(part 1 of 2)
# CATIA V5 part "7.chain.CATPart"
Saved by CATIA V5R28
Part number: Chain
Bounding box of the stored display mesh (mm): x -3.5 to 3.5, y -378.076 to 79.358, z -79.308 to 79.467
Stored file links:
  D:\Catia Cycle design\7.chain.CATPart
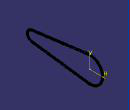
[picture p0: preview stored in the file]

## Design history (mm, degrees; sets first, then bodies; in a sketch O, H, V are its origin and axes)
Set1
  Sketch1 on yz-plane, origin (0, 0, 0), H (0, 1, 0), V (0, 0, 1)
    arc A1 centre (0, 0) radius 75 from (-9.8193, -74.3544) to (-9.8193, 74.3544) ccw
    arc A2 centre (-343.71, 0) radius 30 from (-347.6377, 29.7418) to (-347.6377, -29.7418) ccw
    point P1 (-343.71, 0)
    line L1 (-347.6377, -29.7418) -> (-9.8193, -74.3544)
    line L2 (-347.6377, 29.7418) -> (-9.8193, 74.3544)
    radius A1 = 75
    radius A2 = 30
    distance P1 O = 343.71
    coincidence: P1 H
    tangency: L1 A1, L1 A2, L2 A1, L2 A2
  Sketch2 on yz-plane, origin (0, 0, 0), H (0, 1, 0), V (0, 0, 1)
    circle A1 centre (-9.8193, 74.3544) radius 2.25
    point P1 (-9.8193, 74.3544)
    reference projected point E1 (-9.8193, 74.3544) from vertex [element of Sketch1 | element of Sketch1]
    point P2 (2.1649, 74.9687)
    reference projected arc E2 centre (0, 0) radius 75 from (-9.8193, -74.3544) to (-9.8193, 74.3544) ccw from Sketch1.A1
    circle A2 centre (2.1649, 74.9687) radius 2.25
    circle A3 centre (14.0938, 73.6639) radius 2.25
    circle A4 centre (25.6618, 70.4732) radius 2.25
    circle A5 centre (36.5729, 65.4784) radius 2.25
    circle A6 centre (46.5478, 58.8074) radius 2.25
    circle A7 centre (55.331, 50.6309) radius 2.25
    circle A8 centre (62.6977, 41.1582) radius 2.25
    circle A9 centre (68.4594, 30.6319) radius 2.25
    circle A10 centre (72.4685, 19.3214) radius 2.25
    circle A11 centre (74.6224, 7.5163) radius 2.25
    circle A12 centre (74.866, -4.4812) radius 2.25
    circle A13 centre (73.193, -16.364) radius 2.25
    circle A14 centre (69.6463, -27.8279) radius 2.25
    circle A15 centre (64.3166, -38.5794) radius 2.25
    circle A16 centre (57.3405, -48.3433) radius 2.25
    circle A17 centre (48.8964, -56.8695) radius 2.25
    circle A18 centre (39.2005, -63.94) radius 2.25
    circle A19 centre (28.5012, -69.3735) radius 2.25
    circle A20 centre (17.0722, -73.0311) radius 2.25
    circle A21 centre (5.2061, -74.8191) radius 2.25
    point P23 (-6.7932, -74.6917)
    circle A22 centre (-6.7932, -74.6917) radius 2.25
    point P24 (-18.6979, -73.1819)
    circle A23 centre (-18.6979, -73.1819) radius 2.25
    reference projected line E3 (-347.6377, -29.7418) -> (-9.8193, -74.3544) from Sketch1.L1
    point P25 (-30.5946, -71.6108)
    reference projected line E4 (-347.6377, -29.7418) -> (-9.8193, -74.3544) from Sketch1.L1
    circle A24 centre (-30.5946, -71.6108) radius 2.25
    circle A25 centre (-42.4913, -70.0397) radius 2.25
    circle A26 centre (-54.388, -68.4686) radius 2.25
    circle A27 centre (-66.2847, -66.8976) radius 2.25
    circle A28 centre (-78.1814, -65.3265) radius 2.25
    circle A29 centre (-90.0781, -63.7554) radius 2.25
    circle A30 centre (-101.9748, -62.1843) radius 2.25
    circle A31 centre (-113.8715, -60.6132) radius 2.25
    circle A32 centre (-125.7682, -59.0421) radius 2.25
    circle A33 centre (-137.6649, -57.471) radius 2.25
    circle A34 centre (-149.5616, -55.8999) radius 2.25
    circle A35 centre (-161.4584, -54.3288) radius 2.25
    circle A36 centre (-173.3551, -52.7577) radius 2.25
    circle A37 centre (-185.2518, -51.1866) radius 2.25
    circle A38 centre (-197.1485, -49.6155) radius 2.25
    circle A39 centre (-209.0452, -48.0444) radius 2.25
    circle A40 centre (-220.9419, -46.4734) radius 2.25
    circle A41 centre (-232.8386, -44.9023) radius 2.25
    circle A42 centre (-244.7353, -43.3312) radius 2.25
    circle A43 centre (-256.632, -41.7601) radius 2.25
    circle A44 centre (-268.5287, -40.189) radius 2.25
    circle A45 centre (-280.4254, -38.6179) radius 2.25
    circle A46 centre (-292.3221, -37.0468) radius 2.25
    circle A47 centre (-304.2189, -35.4757) radius 2.25
    circle A48 centre (-316.1156, -33.9046) radius 2.25
    circle A49 centre (-328.0123, -32.3335) radius 2.25
    point P52 (-339.909, -30.7624)
    circle A50 centre (-339.909, -30.7624) radius 2.25
    point P53 (-351.7634, -28.8988)
    circle A51 centre (-351.7634, -28.8988) radius 2.25
    construction circle A52 centre (-343.71, 0) radius 15.1604
    reference projected arc E5 centre (-343.71, 0) radius 30 from (-347.6377, 29.7418) to (-347.6377, -29.7418) ccw from Sketch1.A2
    reference projected arc E6 centre (-343.71, 0) radius 30 from (-347.6377, 29.7418) to (-347.6377, -29.7418) ccw from Sketch1.A2
    point P55 (-362.4451, -23.4307)
    reference projected arc E7 centre (-343.71, 0) radius 30 from (-347.6377, 29.7418) to (-347.6377, -29.7418) ccw from Sketch1.A2
    circle A53 centre (-362.4451, -23.4307) radius 2.25
    circle A54 centre (-370.1292, -14.2136) radius 2.25
    circle A55 centre (-373.5862, -2.7223) radius 2.25
    circle A56 centre (-372.2631, 9.2045) radius 2.25
    circle A57 centre (-366.3714, 19.6586) radius 2.25
    point P61 (-356.8539, 26.9673)
    circle A58 centre (-356.8539, 26.9673) radius 2.25
    point P62 (-345.2582, 30.056)
    circle A59 centre (-345.2582, 30.056) radius 2.25
    reference projected line E8 (-9.8193, 74.3544) -> (-347.6377, 29.7418) from Sketch1.L2
    point P63 (-333.3615, 31.6271)
    reference projected line E9 (-9.8193, 74.3544) -> (-347.6377, 29.7418) from Sketch1.L2
    circle A60 centre (-333.3615, 31.6271) radius 2.25
    circle A61 centre (-321.4648, 33.1982) radius 2.25
    circle A62 centre (-309.5681, 34.7693) radius 2.25
    circle A63 centre (-297.6714, 36.3404) radius 2.25
    circle A64 centre (-285.7747, 37.9115) radius 2.25
    circle A65 centre (-273.878, 39.4826) radius 2.25
    circle A66 centre (-261.9813, 41.0537) radius 2.25
    circle A67 centre (-250.0846, 42.6247) radius 2.25
    circle A68 centre (-238.1878, 44.1958) radius 2.25
    circle A69 centre (-226.2911, 45.7669) radius 2.25
    circle A70 centre (-214.3944, 47.338) radius 2.25
    circle A71 centre (-202.4977, 48.9091) radius 2.25
    circle A72 centre (-190.601, 50.4802) radius 2.25
    circle A73 centre (-178.7043, 52.0513) radius 2.25
    circle A74 centre (-166.8076, 53.6224) radius 2.25
    circle A75 centre (-154.9109, 55.1935) radius 2.25
    circle A76 centre (-143.0142, 56.7646) radius 2.25
    circle A77 centre (-131.1175, 58.3357) radius 2.25
    circle A78 centre (-119.2208, 59.9068) radius 2.25
    circle A79 centre (-107.3241, 61.4778) radius 2.25
    point P84 (-95.4273, 63.0489)
    circle A80 centre (-95.4273, 63.0489) radius 2.25
    point P85 (-81.1513, 64.9343)
    circle A81 centre (-81.1513, 64.9343) radius 2.25
    point P86 (-66.8752, 66.8196)
    reference projected line E10 (-9.8193, 74.3544) -> (-347.6377, 29.7418) from Sketch1.L2
    circle A82 centre (-66.8752, 66.8196) radius 2.25
    circle A83 centre (-52.5992, 68.7049) radius 2.25
    circle A84 centre (-38.3231, 70.5902) radius 2.25
    circle A85 centre (-24.0471, 72.4755) radius 2.25
    radius A1 = 2.25
    distance P1 P2 = 12
    distance P23 P24 = 12
    distance P24 P25 = 12
    distance P52 P53 = 12
    distance P53 P55 = 12
    distance P61 P62 = 12
    distance P62 P63 = 12
    distance P84 P85 = 14.4
    distance P85 P86 = 14.4
    coincidence: P1 E1, P2 E2, P24 E3, P25 E4, P53 E6, P55 E7, P62 E8, P63 E9, P86 E10
    fix: P1, P23, P52, P61, P62, P84
    concentricity: E5 A52
Body1 (main body)
  Pad1: profile Sketch2, direction (1, 0, 0), length 3.5, mirrored extent
  Sketch3 on end face of Pad1, origin (3.5, 0, 0), H (0, 1, 0), V (0, 0, 1)
    arc A1 centre (-9.8193, 74.3544) radius 4.5 from (-8.6557, 78.7014) to (-8.2173, 70.1492) ccw
    circle A2 centre (-9.8193, 74.3544) radius 2.25
    arc A3 centre (2.1649, 74.9687) radius 4.5 from (1.0013, 70.6218) to (0.5629, 79.1739) ccw
    circle A4 centre (2.1649, 74.9687) radius 2.25
    arc A5 centre (-4.777, 93.1912) radius 15 from (-8.6557, 78.7014) to (0.5629, 79.1739) ccw
    arc A6 centre (-2.8774, 56.1319) radius 15 from (-8.2173, 70.1492) to (1.0013, 70.6218) cw
    circle A7 centre (-333.3615, 31.6271) radius 2.25
    circle A8 centre (-321.4648, 33.1982) radius 2.25
    arc A9 centre (-321.4648, 33.1982) radius 4.5 from (-322.2769, 28.7721) to (-323.3981, 37.2617) ccw
    arc A10 centre (-329.8423, 50.8069) radius 15 from (-332.5494, 36.0532) to (-323.3981, 37.2617) ccw
    arc A11 centre (-333.3615, 31.6271) radius 4.5 from (-332.5494, 36.0532) to (-331.4282, 27.5636) ccw
    arc A12 centre (-324.984, 14.0184) radius 15 from (-331.4282, 27.5636) to (-322.2769, 28.7721) cw
    circle A13 centre (-95.4273, 63.0489) radius 2.25
    circle A14 centre (-81.1513, 64.9343) radius 2.25
    arc A15 centre (-81.1513, 64.9343) radius 4.5 from (-82.251, 60.5707) to (-83.3461, 68.8627) ccw
    arc A16 centre (-90.6619, 81.9577) radius 15 from (-94.3276, 67.4125) to (-83.3461, 68.8627) ccw
    arc A17 centre (-95.4273, 63.0489) radius 4.5 from (-94.3276, 67.4125) to (-93.2326, 59.1205) ccw
    arc A18 centre (-85.9167, 46.0255) radius 15 from (-93.2326, 59.1205) to (-82.251, 60.5707) cw
    circle A19 centre (-30.5946, -71.6108) radius 2.25
    circle A20 centre (-18.6979, -73.1819) radius 2.25
    arc A21 centre (-18.6979, -73.1819) radius 4.5 from (-20.6311, -77.2455) to (-19.51, -68.7558) ccw
    arc A22 centre (-22.217, -54.0021) radius 15 from (-28.6613, -67.5473) to (-19.51, -68.7558) ccw
    arc A23 centre (-30.5946, -71.6108) radius 4.5 from (-28.6613, -67.5473) to (-29.7824, -76.0369) ccw
    arc A24 centre (-27.0754, -90.7906) radius 15 from (-29.7824, -76.0369) to (-20.6311, -77.2455) cw
    reference projected point E1 (-9.8193, 74.3544) from vertex [element of Sketch1 | element of Sketch1]
    point P32 (2.1649, 74.9687)
    reference projected circle E2 centre (2.1649, 74.9687) radius 2.25 from edge [face of Pad1 from Sketch2.A2 | end face of Pad1]
    point P33 (14.0938, 73.6639)
    reference projected circle E3 centre (14.0938, 73.6639) radius 2.25 from edge [face of Pad1 from Sketch2.A3 | end face of Pad1]
    point P40 (25.6618, 70.4732)
    arc A25 centre (14.0938, 73.6639) radius 4.5 from (16.567, 77.4233) to (14.2901, 69.1682) ccw
    circle A26 centre (14.0938, 73.6639) radius 2.25
    arc A27 centre (25.6618, 70.4732) radius 4.5 from (23.1886, 66.7138) to (25.4655, 74.9689) ccw
    circle A28 centre (25.6618, 70.4732) radius 2.25
    arc A29 centre (24.8111, 89.9546) radius 15 from (16.567, 77.4233) to (25.4655, 74.9689) ccw
    arc A30 centre (14.9445, 54.1824) radius 15 from (14.2901, 69.1682) to (23.1886, 66.7138) cw
    point P49 (46.5478, 58.8074)
    arc A31 centre (36.5729, 65.4784) radius 4.5 from (40.1041, 68.2678) to (35.3436, 61.1496) ccw
    circle A32 centre (36.5729, 65.4784) radius 2.25
    arc A33 centre (46.5478, 58.8074) radius 4.5 from (43.0165, 56.018) to (47.7771, 63.1362) ccw
    circle A34 centre (46.5478, 58.8074) radius 2.25
    arc A35 centre (51.8749, 77.5656) radius 15 from (40.1041, 68.2678) to (47.7771, 63.1362) ccw
    arc A36 centre (31.2458, 46.7202) radius 15 from (35.3436, 61.1496) to (43.0165, 56.018) cw
    point P58 (62.6977, 41.1582)
    arc A37 centre (55.331, 50.6309) radius 4.5 from (59.5609, 52.1664) to (52.8011, 46.9094) ccw
    circle A38 centre (55.331, 50.6309) radius 2.25
    arc A39 centre (62.6977, 41.1582) radius 4.5 from (58.4678, 39.6227) to (65.2276, 44.8797) ccw
    circle A40 centre (62.6977, 41.1582) radius 2.25
    arc A41 centre (73.6606, 57.2847) radius 15 from (59.5609, 52.1664) to (65.2276, 44.8797) ccw
    arc A42 centre (44.3681, 34.5043) radius 15 from (52.8011, 46.9094) to (58.4678, 39.6227) cw
    point P67 (72.4685, 19.3214)
    arc A43 centre (68.4594, 30.6319) radius 4.5 from (72.9576, 30.7573) to (64.8863, 27.8964) ccw
    circle A44 centre (68.4594, 30.6319) radius 2.25
    arc A45 centre (72.4685, 19.3214) radius 4.5 from (67.9702, 19.196) to (76.0416, 22.057) ccw
    circle A46 centre (72.4685, 19.3214) radius 2.25
    arc A47 centre (87.9518, 31.1754) radius 15 from (72.9576, 30.7573) to (76.0416, 22.057) ccw
    arc A48 centre (52.9761, 18.7779) radius 15 from (64.8863, 27.8964) to (67.9702, 19.196) cw
    point P76 (74.866, -4.4812)
    arc A49 centre (74.6224, 7.5163) radius 4.5 from (78.9313, 6.2189) to (70.3697, 6.0451) ccw
    circle A50 centre (74.6224, 7.5163) radius 2.25
    arc A51 centre (74.866, -4.4812) radius 4.5 from (70.5571, -3.1838) to (79.1187, -3.01) ccw
    circle A52 centre (74.866, -4.4812) radius 2.25
    arc A53 centre (93.2944, 1.8942) radius 15 from (78.9313, 6.2189) to (79.1187, -3.01) ccw
    arc A54 centre (56.1941, 1.1409) radius 15 from (70.3697, 6.0451) to (70.5571, -3.1838) cw
    point P85 (69.6463, -27.8279)
    arc A55 centre (73.193, -16.364) radius 4.5 from (76.8742, -18.9523) to (68.6934, -16.4213) ccw
    circle A56 centre (73.193, -16.364) radius 2.25
    arc A57 centre (69.6463, -27.8279) radius 4.5 from (65.9651, -25.2397) to (74.1459, -27.7707) ccw
    circle A58 centre (69.6463, -27.8279) radius 2.25
    arc A59 centre (89.1447, -27.5798) radius 15 from (76.8742, -18.9523) to (74.1459, -27.7707) ccw
    arc A60 centre (53.6946, -16.6122) radius 15 from (68.6934, -16.4213) to (65.9651, -25.2397) cw
    point P94 (57.3405, -48.3433)
    arc A61 centre (64.3166, -38.5794) radius 4.5 from (66.9955, -42.1952) to (60.0279, -37.2169) ccw
    circle A62 centre (64.3166, -38.5794) radius 2.25
    arc A63 centre (57.3405, -48.3433) radius 4.5 from (54.6616, -44.7275) to (61.6292, -49.7058) ccw
    circle A64 centre (57.3405, -48.3433) radius 2.25
    arc A65 centre (75.9251, -54.2477) radius 15 from (66.9955, -42.1952) to (61.6292, -49.7058) ccw
    arc A66 centre (45.732, -32.675) radius 15 from (60.0279, -37.2169) to (54.6616, -44.7275) cw
    point P103 (39.2005, -63.94)
    arc A67 centre (48.8964, -56.8695) radius 4.5 from (50.3004, -61.1449) to (45.2548, -54.2258) ccw
    circle A68 centre (48.8964, -56.8695) radius 2.25
    arc A69 centre (39.2005, -63.94) radius 4.5 from (37.7965, -59.6646) to (42.8421, -66.5837) ccw
    circle A70 centre (39.2005, -63.94) radius 2.25
    arc A71 centre (54.9805, -75.3961) radius 15 from (50.3004, -61.1449) to (42.8421, -66.5837) ccw
    arc A72 centre (33.1164, -45.4134) radius 15 from (45.2548, -54.2258) to (37.7965, -59.6646) cw
    point P112 (17.0722, -73.0311)
    arc A73 centre (28.5012, -69.3735) radius 4.5 from (28.4875, -73.8735) to (25.8774, -65.7176) ccw
    circle A74 centre (28.5012, -69.3735) radius 2.25
    arc A75 centre (17.0722, -73.0311) radius 4.5 from (17.0858, -68.5311) to (19.6959, -76.687) ccw
    circle A76 centre (17.0722, -73.0311) radius 2.25
    arc A77 centre (28.4419, -88.8734) radius 15 from (28.4875, -73.8735) to (19.6959, -76.687) ccw
    arc A78 centre (17.1314, -53.5312) radius 15 from (25.8774, -65.7176) to (17.0858, -68.5311) cw
    point P121 (-6.7932, -74.6917)
    arc A79 centre (5.2061, -74.8191) radius 4.5 from (3.7761, -79.0858) to (3.867, -70.5229) ccw
    circle A80 centre (5.2061, -74.8191) radius 2.25
    arc A81 centre (-6.7932, -74.6917) radius 4.5 from (-5.3632, -70.425) to (-5.4541, -78.9879) ccw
    circle A82 centre (-6.7932, -74.6917) radius 2.25
    arc A83 centre (-0.9905, -93.3083) radius 15 from (3.7761, -79.0858) to (-5.4541, -78.9879) ccw
    arc A84 centre (-0.5966, -56.2025) radius 15 from (3.867, -70.5229) to (-5.3632, -70.425) cw
    point P124 (-30.5946, -71.6108)
    point P125 (-18.6979, -73.1819)
    reference projected circle E4 centre (-18.6979, -73.1819) radius 2.25 from edge [face of Pad1 from Sketch2.A23 | end face of Pad1]
    reference projected circle E5 centre (-30.5946, -71.6108) radius 2.25 from edge [face of Pad1 from Sketch2.A24 | end face of Pad1]
    reference projected circle E6 centre (-18.6979, -73.1819) radius 2.25 from edge [face of Pad1 from Sketch2.A23 | end face of Pad1]
    point P126 (-42.4913, -70.0397)
    reference projected circle E7 centre (-42.4913, -70.0397) radius 2.25 from edge [face of Pad1 from Sketch2.A25 | end face of Pad1]
    point P133 (-54.388, -68.4686)
    point P134 (-42.4913, -70.0397)
    circle A85 centre (-54.388, -68.4686) radius 2.25
    circle A86 centre (-42.4913, -70.0397) radius 2.25
    arc A87 centre (-42.4913, -70.0397) radius 4.5 from (-44.4245, -74.1033) to (-43.3034, -65.6136) ccw
    arc A88 centre (-46.0105, -50.8599) radius 15 from (-52.4547, -64.4051) to (-43.3034, -65.6136) ccw
    arc A89 centre (-54.388, -68.4686) radius 4.5 from (-52.4547, -64.4051) to (-53.5759, -72.8948) ccw
    arc A90 centre (-50.8688, -87.6485) radius 15 from (-53.5759, -72.8948) to (-44.4245, -74.1033) cw
    point P142 (-78.1814, -65.3265)
    point P143 (-66.2847, -66.8976)
    circle A91 centre (-78.1814, -65.3265) radius 2.25
    circle A92 centre (-66.2847, -66.8976) radius 2.25
    arc A93 centre (-66.2847, -66.8976) radius 4.5 from (-68.218, -70.9611) to (-67.0968, -62.4714) ccw
    arc A94 centre (-69.8039, -47.7177) radius 15 from (-76.2481, -61.2629) to (-67.0968, -62.4714) ccw
    arc A95 centre (-78.1814, -65.3265) radius 4.5 from (-76.2481, -61.2629) to (-77.3693, -69.7526) ccw
    arc A96 centre (-74.6622, -84.5063) radius 15 from (-77.3693, -69.7526) to (-68.218, -70.9611) cw
    point P151 (-101.9748, -62.1843)
    point P152 (-90.0781, -63.7554)
    circle A97 centre (-101.9748, -62.1843) radius 2.25
    circle A98 centre (-90.0781, -63.7554) radius 2.25
    arc A99 centre (-90.0781, -63.7554) radius 4.5 from (-92.0114, -67.8189) to (-90.8902, -59.3293) ccw
    arc A100 centre (-93.5973, -44.5756) radius 15 from (-100.0415, -58.1207) to (-90.8902, -59.3293) ccw
    arc A101 centre (-101.9748, -62.1843) radius 4.5 from (-100.0415, -58.1207) to (-101.1627, -66.6104) ccw
    arc A102 centre (-98.4556, -81.3641) radius 15 from (-101.1627, -66.6104) to (-92.0114, -67.8189) cw
    point P160 (-125.7682, -59.0421)
    point P161 (-113.8715, -60.6132)
    circle A103 centre (-125.7682, -59.0421) radius 2.25
    circle A104 centre (-113.8715, -60.6132) radius 2.25
    arc A105 centre (-113.8715, -60.6132) radius 4.5 from (-115.8048, -64.6767) to (-114.6836, -56.1871) ccw
    arc A106 centre (-117.3907, -41.4334) radius 15 from (-123.835, -54.9785) to (-114.6836, -56.1871) ccw
    arc A107 centre (-125.7682, -59.0421) radius 4.5 from (-123.835, -54.9785) to (-124.9561, -63.4682) ccw
    arc A108 centre (-122.249, -78.2219) radius 15 from (-124.9561, -63.4682) to (-115.8048, -64.6767) cw
    point P169 (-149.5616, -55.8999)
    point P170 (-137.6649, -57.471)
    circle A109 centre (-149.5616, -55.8999) radius 2.25
    circle A110 centre (-137.6649, -57.471) radius 2.25
    arc A111 centre (-137.6649, -57.471) radius 4.5 from (-139.5982, -61.5346) to (-138.4771, -53.0449) ccw
    arc A112 centre (-141.1841, -38.2912) radius 15 from (-147.6284, -51.8364) to (-138.4771, -53.0449) ccw
    arc A113 centre (-149.5616, -55.8999) radius 4.5 from (-147.6284, -51.8364) to (-148.7495, -60.326) ccw
    arc A114 centre (-146.0425, -75.0797) radius 15 from (-148.7495, -60.326) to (-139.5982, -61.5346) cw
    point P178 (-173.3551, -52.7577)
    point P179 (-161.4584, -54.3288)
    circle A115 centre (-173.3551, -52.7577) radius 2.25
    circle A116 centre (-161.4584, -54.3288) radius 2.25
    arc A117 centre (-161.4584, -54.3288) radius 4.5 from (-163.3916, -58.3924) to (-162.2705, -49.9027) ccw
    arc A118 centre (-164.9775, -35.149) radius 15 from (-171.4218, -48.6942) to (-162.2705, -49.9027) ccw
    arc A119 centre (-173.3551, -52.7577) radius 4.5 from (-171.4218, -48.6942) to (-172.5429, -57.1838) ccw
    arc A120 centre (-169.8359, -71.9375) radius 15 from (-172.5429, -57.1838) to (-163.3916, -58.3924) cw
    point P187 (-197.1485, -49.6155)
    point P188 (-185.2518, -51.1866)
    circle A121 centre (-197.1485, -49.6155) radius 2.25
    circle A122 centre (-185.2518, -51.1866) radius 2.25
    arc A123 centre (-185.2518, -51.1866) radius 4.5 from (-187.185, -55.2502) to (-186.0639, -46.7605) ccw
    arc A124 centre (-188.771, -32.0068) radius 15 from (-195.2152, -45.552) to (-186.0639, -46.7605) ccw
    arc A125 centre (-197.1485, -49.6155) radius 4.5 from (-195.2152, -45.552) to (-196.3364, -54.0417) ccw
    arc A126 centre (-193.6293, -68.7954) radius 15 from (-196.3364, -54.0417) to (-187.185, -55.2502) cw
    point P196 (-220.9419, -46.4734)
    point P197 (-209.0452, -48.0444)
    circle A127 centre (-220.9419, -46.4734) radius 2.25
    circle A128 centre (-209.0452, -48.0444) radius 2.25
    arc A129 centre (-209.0452, -48.0444) radius 4.5 from (-210.9785, -52.108) to (-209.8573, -43.6183) ccw
    arc A130 centre (-212.5644, -28.8646) radius 15 from (-219.0086, -42.4098) to (-209.8573, -43.6183) ccw
    arc A131 centre (-220.9419, -46.4734) radius 4.5 from (-219.0086, -42.4098) to (-220.1298, -50.8995) ccw
    arc A132 centre (-217.4227, -65.6532) radius 15 from (-220.1298, -50.8995) to (-210.9785, -52.108) cw
    point P205 (-244.7353, -43.3312)
    point P206 (-232.8386, -44.9023)
    circle A133 centre (-244.7353, -43.3312) radius 2.25
    circle A134 centre (-232.8386, -44.9023) radius 2.25
    arc A135 centre (-232.8386, -44.9023) radius 4.5 from (-234.7719, -48.9658) to (-233.6507, -40.4762) ccw
    arc A136 centre (-236.3578, -25.7224) radius 15 from (-242.802, -39.2676) to (-233.6507, -40.4762) ccw
    arc A137 centre (-244.7353, -43.3312) radius 4.5 from (-242.802, -39.2676) to (-243.9232, -47.7573) ccw
    arc A138 centre (-241.2161, -62.511) radius 15 from (-243.9232, -47.7573) to (-234.7719, -48.9658) cw
    point P214 (-268.5287, -40.189)
    point P215 (-256.632, -41.7601)
    circle A139 centre (-268.5287, -40.189) radius 2.25
    circle A140 centre (-256.632, -41.7601) radius 2.25
    arc A141 centre (-256.632, -41.7601) radius 4.5 from (-258.5653, -45.8236) to (-257.4441, -37.334) ccw
    arc A142 centre (-260.1512, -22.5803) radius 15 from (-266.5955, -36.1254) to (-257.4441, -37.334) ccw
    arc A143 centre (-268.5287, -40.189) radius 4.5 from (-266.5955, -36.1254) to (-267.7166, -44.6151) ccw
    arc A144 centre (-265.0095, -59.3688) radius 15 from (-267.7166, -44.6151) to (-258.5653, -45.8236) cw
    point P223 (-292.3221, -37.0468)
    point P224 (-280.4254, -38.6179)
    circle A145 centre (-292.3221, -37.0468) radius 2.25
    circle A146 centre (-280.4254, -38.6179) radius 2.25
    arc A147 centre (-280.4254, -38.6179) radius 4.5 from (-282.3587, -42.6814) to (-281.2376, -34.1918) ccw
    arc A148 centre (-283.9446, -19.4381) radius 15 from (-290.3889, -32.9833) to (-281.2376, -34.1918) ccw
    arc A149 centre (-292.3221, -37.0468) radius 4.5 from (-290.3889, -32.9833) to (-291.51, -41.4729) ccw
    arc A150 centre (-288.803, -56.2266) radius 15 from (-291.51, -41.4729) to (-282.3587, -42.6814) cw
    point P232 (-316.1156, -33.9046)
    point P233 (-304.2189, -35.4757)
    circle A151 centre (-316.1156, -33.9046) radius 2.25
    circle A152 centre (-304.2189, -35.4757) radius 2.25
    arc A153 centre (-304.2189, -35.4757) radius 4.5 from (-306.1521, -39.5393) to (-305.031, -31.0496) ccw
    arc A154 centre (-307.738, -16.2959) radius 15 from (-314.1823, -29.8411) to (-305.031, -31.0496) ccw
    arc A155 centre (-316.1156, -33.9046) radius 4.5 from (-314.1823, -29.8411) to (-315.3034, -38.3307) ccw
    arc A156 centre (-312.5964, -53.0844) radius 15 from (-315.3034, -38.3307) to (-306.1521, -39.5393) cw
    point P241 (-339.909, -30.7624)
    point P242 (-328.0123, -32.3335)
    circle A157 centre (-339.909, -30.7624) radius 2.25
    circle A158 centre (-328.0123, -32.3335) radius 2.25
    arc A159 centre (-328.0123, -32.3335) radius 4.5 from (-329.9455, -36.3971) to (-328.8244, -27.9074) ccw
    arc A160 centre (-331.5315, -13.1537) radius 15 from (-337.9757, -26.6989) to (-328.8244, -27.9074) ccw
    arc A161 centre (-339.909, -30.7624) radius 4.5 from (-337.9757, -26.6989) to (-339.0969, -35.1885) ccw
    arc A162 centre (-336.3898, -49.9423) radius 15 from (-339.0969, -35.1885) to (-329.9455, -36.3971) cw
    circle A163 centre (-362.4451, -23.4307) radius 2.25
    circle A164 centre (-351.7634, -28.8988) radius 2.25
    arc A165 centre (-351.7634, -28.8988) radius 4.5 from (-354.947, -32.0792) to (-351.0448, -24.4566) ccw
    arc A166 centre (-348.6495, -9.6491) radius 15 from (-359.2615, -20.2503) to (-351.0448, -24.4566) ccw
    arc A167 centre (-362.4451, -23.4307) radius 4.5 from (-359.2615, -20.2503) to (-363.1637, -27.8729) ccw
    arc A168 centre (-365.5589, -42.6804) radius 15 from (-363.1637, -27.8729) to (-354.947, -32.0792) cw
    point P252 (-351.7634, -28.8988)
    point P253 (-362.4451, -23.4307)
    point P254 (-370.1292, -14.2136)
    reference projected circle E8 centre (-351.7634, -28.8988) radius 2.25 from edge [face of Pad1 from Sketch2.A51 | end face of Pad1]
    reference projected circle E9 centre (-362.4451, -23.4307) radius 2.25 from edge [face of Pad1 from Sketch2.A53 | end face of Pad1]
    reference projected circle E10 centre (-370.1292, -14.2136) radius 2.25 from edge [face of Pad1 from Sketch2.A54 | end face of Pad1]
    construction circle A169 centre (-343.71, 0) radius 8.6889
    reference projected arc E11 centre (-343.71, 0) radius 30 from (-347.6377, 29.7418) to (-347.6377, -29.7418) ccw from Sketch1.A2
    point P262 (-370.1292, -14.2136)
    point P263 (-373.5862, -2.7223)
    circle A170 centre (-373.5862, -2.7223) radius 2.25
    circle A171 centre (-370.1292, -14.2136) radius 2.25
    arc A172 centre (-370.1292, -14.2136) radius 4.5 from (-374.6283, -14.1212) to (-366.4279, -11.6542) ccw
    arc A173 centre (-354.0903, -3.1228) radius 15 from (-369.0872, -2.8147) to (-366.4279, -11.6542) ccw
    arc A174 centre (-373.5862, -2.7223) radius 4.5 from (-369.0872, -2.8147) to (-377.2875, -5.2817) ccw
    arc A175 centre (-389.6251, -13.8131) radius 15 from (-377.2875, -5.2817) to (-374.6283, -14.1212) cw
    point P272 (-372.2631, 9.2045)
    point P273 (-366.3714, 19.6586)
    circle A176 centre (-366.3714, 19.6586) radius 2.25
    circle A177 centre (-372.2631, 9.2045) radius 2.25
    arc A178 centre (-372.2631, 9.2045) radius 4.5 from (-375.3134, 12.5129) to (-367.8531, 8.3086) ccw
    arc A179 centre (-353.1535, 5.3221) radius 15 from (-363.3211, 16.3502) to (-367.8531, 8.3086) ccw
    arc A180 centre (-366.3714, 19.6586) radius 4.5 from (-363.3211, 16.3502) to (-370.7813, 20.5546) ccw
    arc A181 centre (-385.481, 23.541) radius 15 from (-370.7813, 20.5546) to (-375.3134, 12.5129) cw
    point P282 (-356.8539, 26.9673)
    point P283 (-345.2334, 29.9613)
    circle A182 centre (-345.2334, 29.9613) radius 2.25
    circle A183 centre (-356.8539, 26.9673) radius 2.25
    arc A184 centre (-356.8539, 26.9673) radius 4.5 from (-356.5814, 31.4591) to (-354.4448, 23.1665) ccw
    arc A185 centre (-346.4145, 10.4971) radius 15 from (-345.506, 25.4696) to (-354.4448, 23.1665) ccw
    arc A186 centre (-345.2334, 29.9613) radius 4.5 from (-345.506, 25.4696) to (-347.6425, 33.7621) ccw
    arc A187 centre (-355.6728, 46.4315) radius 15 from (-347.6425, 33.7621) to (-356.5814, 31.4591) cw
    point P286 (-333.3615, 31.6271)
    point P287 (-321.4648, 33.1982)
    point P288 (-309.5681, 34.7693)
    reference projected circle E12 centre (-333.3615, 31.6271) radius 2.25 from edge [face of Pad1 from Sketch2.A60 | end face of Pad1]
    reference projected circle E13 centre (-321.4648, 33.1982) radius 2.25 from edge [face of Pad1 from Sketch2.A61 | end face of Pad1]
    reference projected circle E14 centre (-309.5681, 34.7693) radius 2.25 from edge [face of Pad1 from Sketch2.A62 | end face of Pad1]
    point P295 (-309.5681, 34.7693)
    point P296 (-297.6714, 36.3404)
    point P297 (-285.7747, 37.9115)
    circle A188 centre (-309.5681, 34.7693) radius 2.25
    circle A189 centre (-297.6714, 36.3404) radius 2.25
    arc A190 centre (-297.6714, 36.3404) radius 4.5 from (-298.4835, 31.9143) to (-299.6047, 40.4039) ccw
    arc A191 centre (-306.0489, 53.9491) radius 15 from (-308.756, 39.1954) to (-299.6047, 40.4039) ccw
    arc A192 centre (-309.5681, 34.7693) radius 4.5 from (-308.756, 39.1954) to (-307.6348, 30.7057) ccw
    arc A193 centre (-301.1906, 17.1606) radius 15 from (-307.6348, 30.7057) to (-298.4835, 31.9143) cw
    point P306 (-285.7747, 37.9115)
    point P307 (-273.878, 39.4826)
    point P308 (-261.9813, 41.0537)
    circle A194 centre (-285.7747, 37.9115) radius 2.25
    circle A195 centre (-273.878, 39.4826) radius 2.25
    arc A196 centre (-273.878, 39.4826) radius 4.5 from (-274.6901, 35.0565) to (-275.8112, 43.5461) ccw
    arc A197 centre (-282.2555, 57.0913) radius 15 from (-284.9626, 42.3376) to (-275.8112, 43.5461) ccw
    arc A198 centre (-285.7747, 37.9115) radius 4.5 from (-284.9626, 42.3376) to (-283.8414, 33.8479) ccw
    arc A199 centre (-277.3972, 20.3027) radius 15 from (-283.8414, 33.8479) to (-274.6901, 35.0565) cw
    point P317 (-261.9813, 41.0537)
    point P318 (-250.0846, 42.6247)
    point P319 (-238.1878, 44.1958)
    circle A200 centre (-261.9813, 41.0537) radius 2.25
    circle A201 centre (-250.0846, 42.6247) radius 2.25
    arc A202 centre (-250.0846, 42.6247) radius 4.5 from (-250.8967, 38.1986) to (-252.0178, 46.6883) ccw
    arc A203 centre (-258.4621, 60.2335) radius 15 from (-261.1691, 45.4798) to (-252.0178, 46.6883) ccw
    arc A204 centre (-261.9813, 41.0537) radius 4.5 from (-261.1691, 45.4798) to (-260.048, 36.9901) ccw
    arc A205 centre (-253.6037, 23.4449) radius 15 from (-260.048, 36.9901) to (-250.8967, 38.1986) cw
    point P328 (-238.1878, 44.1958)
    point P329 (-226.2911, 45.7669)
    point P330 (-214.3944, 47.338)
    circle A206 centre (-238.1878, 44.1958) radius 2.25
    circle A207 centre (-226.2911, 45.7669) radius 2.25
    arc A208 centre (-226.2911, 45.7669) radius 4.5 from (-227.1033, 41.3408) to (-228.2244, 49.8305) ccw
    arc A209 centre (-234.6687, 63.3757) radius 15 from (-237.3757, 48.6219) to (-228.2244, 49.8305) ccw
    arc A210 centre (-238.1878, 44.1958) radius 4.5 from (-237.3757, 48.6219) to (-236.2546, 40.1323) ccw
    arc A211 centre (-229.8103, 26.5871) radius 15 from (-236.2546, 40.1323) to (-227.1033, 41.3408) cw
    point P339 (-214.3944, 47.338)
    point P340 (-202.4977, 48.9091)
    point P341 (-190.601, 50.4802)
    circle A212 centre (-214.3944, 47.338) radius 2.25
    circle A213 centre (-202.4977, 48.9091) radius 2.25
    arc A214 centre (-202.4977, 48.9091) radius 4.5 from (-203.3098, 44.483) to (-204.431, 52.9727) ccw
    arc A215 centre (-210.8752, 66.5178) radius 15 from (-213.5823, 51.7641) to (-204.431, 52.9727) ccw
    arc A216 centre (-214.3944, 47.338) radius 4.5 from (-213.5823, 51.7641) to (-212.4612, 43.2745) ccw
    arc A217 centre (-206.0169, 29.7293) radius 15 from (-212.4612, 43.2745) to (-203.3098, 44.483) cw
    point P350 (-190.601, 50.4802)
    point P351 (-178.7043, 52.0513)
    point P352 (-166.8076, 53.6224)
    circle A218 centre (-190.601, 50.4802) radius 2.25
    circle A219 centre (-178.7043, 52.0513) radius 2.25
    arc A220 centre (-178.7043, 52.0513) radius 4.5 from (-179.5164, 47.6252) to (-180.6376, 56.1148) ccw
    arc A221 centre (-187.0818, 69.66) radius 15 from (-189.7889, 54.9063) to (-180.6376, 56.1148) ccw
    arc A222 centre (-190.601, 50.4802) radius 4.5 from (-189.7889, 54.9063) to (-188.6677, 46.4167) ccw
    arc A223 centre (-182.2235, 32.8715) radius 15 from (-188.6677, 46.4167) to (-179.5164, 47.6252) cw
    point P361 (-166.8076, 53.6224)
    point P362 (-154.9109, 55.1935)
    point P363 (-143.0142, 56.7646)
    circle A224 centre (-166.8076, 53.6224) radius 2.25
    circle A225 centre (-154.9109, 55.1935) radius 2.25
    arc A226 centre (-154.9109, 55.1935) radius 4.5 from (-155.723, 50.7674) to (-156.8442, 59.257) ccw
    arc A227 centre (-163.2884, 72.8022) radius 15 from (-165.9955, 58.0485) to (-156.8442, 59.257) ccw
    arc A228 centre (-166.8076, 53.6224) radius 4.5 from (-165.9955, 58.0485) to (-164.8743, 49.5588) ccw
    arc A229 centre (-158.4301, 36.0137) radius 15 from (-164.8743, 49.5588) to (-155.723, 50.7674) cw
    point P372 (-143.0142, 56.7646)
    point P373 (-131.1175, 58.3357)
    point P374 (-119.2208, 59.9068)
    circle A230 centre (-143.0142, 56.7646) radius 2.25
    circle A231 centre (-131.1175, 58.3357) radius 2.25
    arc A232 centre (-131.1175, 58.3357) radius 4.5 from (-131.9296, 53.9096) to (-133.0507, 62.3992) ccw
    arc A233 centre (-139.495, 75.9444) radius 15 from (-142.2021, 61.1907) to (-133.0507, 62.3992) ccw
    arc A234 centre (-143.0142, 56.7646) radius 4.5 from (-142.2021, 61.1907) to (-141.0809, 52.701) ccw
    arc A235 centre (-134.6367, 39.1559) radius 15 from (-141.0809, 52.701) to (-131.9296, 53.9096) cw
    point P383 (-119.2208, 59.9068)
    point P384 (-107.3241, 61.4778)
    point P385 (-95.4273, 63.0489)
    circle A236 centre (-119.2208, 59.9068) radius 2.25
    circle A237 centre (-107.3241, 61.4778) radius 2.25
    arc A238 centre (-107.3241, 61.4778) radius 4.5 from (-108.1362, 57.0517) to (-109.2573, 65.5414) ccw
    arc A239 centre (-115.7016, 79.0866) radius 15 from (-118.4086, 64.3329) to (-109.2573, 65.5414) ccw
    arc A240 centre (-119.2208, 59.9068) radius 4.5 from (-118.4086, 64.3329) to (-117.2875, 55.8432) ccw
    arc A241 centre (-110.8432, 42.298) radius 15 from (-117.2875, 55.8432) to (-108.1362, 57.0517) cw
    point P388 (-95.4273, 63.0489)
    point P389 (-81.1513, 64.9343)
    point P390 (-66.8752, 66.8196)
    reference projected circle E15 centre (-95.4273, 63.0489) radius 2.25 from edge [face of Pad1 from Sketch2.A80 | end face of Pad1]
    reference projected circle E16 centre (-81.1513, 64.9343) radius 2.25 from edge [face of Pad1 from Sketch2.A81 | end face of Pad1]
    reference projected circle E17 centre (-66.8752, 66.8196) radius 2.25 from edge [face of Pad1 from Sketch2.A82 | end face of Pad1]
    reference projected circle E18 centre (-81.1513, 64.9343) radius 2.25 from edge [face of Pad1 from Sketch2.A81 | end face of Pad1]
    point P397 (-66.8752, 66.8196)
    point P398 (-66.8752, 66.8196)
    point P399 (-52.5992, 68.7049)
    circle A242 centre (-66.8752, 66.8196) radius 2.25
    circle A243 centre (-52.5992, 68.7049) radius 2.25
    arc A244 centre (-52.5992, 68.7049) radius 4.5 from (-53.6989, 64.3413) to (-54.794, 72.6334) ccw
    arc A245 centre (-62.1098, 85.7283) radius 15 from (-65.7755, 71.1831) to (-54.794, 72.6334) ccw
    arc A246 centre (-66.8752, 66.8196) radius 4.5 from (-65.7755, 71.1831) to (-64.6805, 62.8911) ccw
    arc A247 centre (-57.3646, 49.7961) radius 15 from (-64.6805, 62.8911) to (-53.6989, 64.3413) cw
    point P408 (-38.3231, 70.5902)
    point P409 (-38.3231, 70.5902)
    point P410 (-24.0471, 72.4755)
    circle A248 centre (-38.3231, 70.5902) radius 2.25
    circle A249 centre (-24.0471, 72.4755) radius 2.25
    arc A250 centre (-24.0471, 72.4755) radius 4.5 from (-25.1468, 68.1119) to (-26.2419, 76.404) ccw
    arc A251 centre (-33.5577, 89.4989) radius 15 from (-37.2234, 74.9537) to (-26.2419, 76.404) ccw
    arc A252 centre (-38.3231, 70.5902) radius 4.5 from (-37.2234, 74.9537) to (-36.1284, 66.6617) ccw
    arc A253 centre (-28.8125, 53.5667) radius 15 from (-36.1284, 66.6617) to (-25.1468, 68.1119) cw
    radius A2 = 2.25
    radius A1 = 4.5
    radius A4 = 2.25
    radius A3 = 4.5
    radius A5 = 15
    radius A6 = 15
    radius A7 = 2.25
    radius A8 = 2.25
    radius A9 = 4.5
    radius A12 = 15
    radius A13 = 2.25
    radius A14 = 2.25
    radius A15 = 4.5
    radius A18 = 15
    radius A19 = 2.25
    radius A20 = 2.25
    radius A21 = 4.5
    radius A24 = 15
    radius A23 = 4.5
    radius A22 = 15
    radius A163 = 2.25
    radius A164 = 2.25
    radius A165 = 4.5
    radius A168 = 15
    radius A167 = 4.5
    radius A163 = 2.25 (reference)
    radius A166 = 15
    radius A11 = 4.5
    radius A7 = 2.25 (reference)
    radius A10 = 15
    radius A17 = 4.5
    radius A13 = 2.25 (reference)
    radius A16 = 15
    tangency: A5 A3, A5 A1, A6 A1, A3 A6, A10 A9, A10 A11, A12 A11, A9 A12, A16 A15, A16 A17, A18 A17, A15 A18, A22 A21, A22 A23, A24 A23, A21 A24, A166 A165, A166 A167, A168 A167, A165 A168
    concentricity: E1 A2, P32 E2, A4 P32, E3 P33, P125 E4, P124 E5, A19 P124, A20 E6, P126 E7, P252 E8, P253 E9, P254 E10, A164 P252, A163 P253, E11 A169, P286 E12, P287 E13, P288 E14, A7 P286, A8 P287, P388 E15, P389 E16, P390 E17, A13 P388, A14 E18
  Pad2: profile Sketch3, direction (-1, 0, 0), length 1.5, opposite side length -0.5
  Mirror1: of Pad2, about yz-plane
  Sketch4 on yz-plane, origin (0, 0, 0), H (0, 1, 0), V (0, 0, 1)
    point P1 (13.183, 78.0707)
    point P2 (25.6618, 70.4732)
    reference projected circle E1 centre (25.6618, 70.4732) radius 2.25 from edge [face of Pad1 from Sketch2.A4 | end face of Pad1]
    point P7 (37.0961, 69.9479)
    arc A1 centre (25.6618, 70.4732) radius 4.5 from (28.703, 73.79) to (25.1386, 66.0037) ccw
    circle A2 centre (25.6618, 70.4732) radius 2.25
    circle A3 centre (36.5729, 65.4784) radius 2.25
    arc A4 centre (36.5729, 65.4784) radius 4.5 from (33.5318, 62.1616) to (37.0961, 69.9479) ccw
    arc A5 centre (38.8401, 84.8462) radius 15 from (28.703, 73.79) to (37.0961, 69.9479) ccw
    arc A6 centre (23.3946, 51.1054) radius 15 from (25.1386, 66.0037) to (33.5318, 62.1616) cw
    point P16 (57.235, 54.7082)
    arc A7 centre (46.5478, 58.8074) radius 4.5 from (50.4786, 60.9978) to (44.6438, 54.73) ccw
    circle A8 centre (46.5478, 58.8074) radius 2.25
    circle A9 centre (55.331, 50.6309) radius 2.25
    arc A10 centre (55.331, 50.6309) radius 4.5 from (51.4001, 48.4404) to (57.235, 54.7082) ccw
    arc A11 centre (63.5816, 68.2994) radius 15 from (50.4786, 60.9978) to (57.235, 54.7082) ccw
    arc A12 centre (38.2971, 41.1388) radius 15 from (44.6438, 54.73) to (51.4001, 48.4404) cw
    point P24 (71.5504, 33.9023)
    arc A13 centre (62.6977, 41.1582) radius 4.5 from (67.1184, 41.9994) to (59.6067, 37.8878) ccw
    circle A14 centre (62.6977, 41.1582) radius 2.25
    circle A15 centre (68.4594, 30.6319) radius 2.25
    arc A16 centre (68.4594, 30.6319) radius 4.5 from (64.0387, 29.7907) to (71.5504, 33.9023) ccw
    arc A17 centre (81.8539, 44.8036) radius 15 from (67.1184, 41.9994) to (71.5504, 33.9023) ccw
    arc A18 centre (49.3031, 26.9866) radius 15 from (59.6067, 37.8878) to (64.0387, 29.7907) cw
    point P33 (78.586, 9.647)
    arc A19 centre (72.4685, 19.3214) radius 4.5 from (76.9292, 18.7278) to (68.5049, 17.1908) ccw
    circle A20 centre (72.4685, 19.3214) radius 2.25
    circle A21 centre (74.6224, 7.5163) radius 2.25
    arc A22 centre (74.6224, 7.5163) radius 4.5 from (70.1617, 8.1099) to (78.586, 9.647) ccw
    arc A23 centre (91.7981, 16.7492) radius 15 from (76.9292, 18.7278) to (78.586, 9.647) ccw
    arc A24 centre (55.2928, 10.0885) radius 15 from (68.5049, 17.1908) to (70.1617, 8.1099) cw
    point P42 (77.6259, -15.5899)
    arc A25 centre (74.866, -4.4812) radius 4.5 from (78.9128, -6.4492) to (70.4331, -5.2554) ccw
    circle A26 centre (74.866, -4.4812) radius 2.25
    circle A27 centre (73.193, -16.364) radius 2.25
    arc A28 centre (73.193, -16.364) radius 4.5 from (69.1462, -14.396) to (77.6259, -15.5899) ccw
    arc A29 centre (92.4023, -13.0093) radius 15 from (78.9128, -6.4492) to (77.6259, -15.5899) ccw
    arc A30 centre (55.6567, -7.8359) radius 15 from (70.4331, -5.2554) to (69.1462, -14.396) cw
    point P51 (68.7678, -39.2405)
    arc A31 centre (69.6463, -27.8279) radius 4.5 from (72.8675, -30.9701) to (65.1951, -27.1668) ccw
    circle A32 centre (69.6463, -27.8279) radius 2.25
    circle A33 centre (64.3166, -38.5794) radius 2.25
    arc A34 centre (64.3166, -38.5794) radius 4.5 from (61.0954, -35.4372) to (68.7678, -39.2405) ccw
    arc A35 centre (83.605, -41.4442) radius 15 from (72.8675, -30.9701) to (68.7678, -39.2405) ccw
    arc A36 centre (50.3579, -24.9631) radius 15 from (65.1951, -27.1668) to (61.0954, -35.4372) cw
    point P60 (52.9129, -58.8987)
    arc A37 centre (57.3405, -48.3433) radius 4.5 from (59.4084, -52.34) to (53.3239, -46.3142) ccw
    circle A38 centre (57.3405, -48.3433) radius 2.25
    circle A39 centre (48.8964, -56.8695) radius 2.25
    arc A40 centre (48.8964, -56.8695) radius 4.5 from (46.8285, -52.8728) to (52.9129, -58.8987) ccw
    arc A41 centre (66.3014, -65.6624) radius 15 from (59.4084, -52.34) to (52.9129, -58.8987) ccw
    arc A42 centre (39.9354, -39.5505) radius 15 from (53.3239, -46.3142) to (46.8285, -52.8728) cw
    point P69 (31.6744, -72.5642)
    arc A43 centre (39.2005, -63.94) radius 4.5 from (39.9047, -68.3845) to (36.0273, -60.7493) ccw
    circle A44 centre (39.2005, -63.94) radius 2.25
    circle A45 centre (28.5012, -69.3735) radius 2.25
    arc A46 centre (28.5012, -69.3735) radius 4.5 from (27.797, -64.9289) to (31.6744, -72.5642) ccw
    arc A47 centre (42.252, -83.1997) radius 15 from (39.9047, -68.3845) to (31.6744, -72.5642) ccw
    arc A48 centre (25.4497, -50.1137) radius 15 from (36.0273, -60.7493) to (27.797, -64.9289) cw
    point P78 (7.2132, -78.8467)
    arc A49 centre (17.0722, -73.0311) radius 4.5 from (16.341, -77.4713) to (15.065, -69.0035) ccw
    circle A50 centre (17.0722, -73.0311) radius 2.25
    circle A51 centre (5.2061, -74.8191) radius 2.25
    arc A52 centre (5.2061, -74.8191) radius 4.5 from (5.9373, -70.3789) to (7.2132, -78.8467) ccw
    arc A53 centre (13.9037, -92.272) radius 15 from (16.341, -77.4713) to (7.2132, -78.8467) ccw
    arc A54 centre (8.3746, -55.5782) radius 15 from (15.065, -69.0035) to (5.9373, -70.3789) cw
    point P83 (13.183, 78.0707)
    arc A55 centre (-18.6979, -73.1819) radius 4.5 from (-16.7855, -69.1085) to (-17.8629, -77.6038) ccw
    arc A56 centre (-6.7932, -74.6917) radius 4.5 from (-8.7055, -78.7652) to (-7.6281, -70.2698) ccw
    circle A57 centre (-6.7932, -74.6917) radius 2.25
    circle A58 centre (-18.6979, -73.1819) radius 2.25
    arc A59 centre (-10.4111, -55.5303) radius 15 from (-16.7855, -69.1085) to (-7.6281, -70.2698) ccw
    arc A60 centre (-15.0799, -92.3434) radius 15 from (-17.8629, -77.6038) to (-8.7055, -78.7652) cw
    arc A61 centre (-42.4913, -70.0397) radius 4.5 from (-40.558, -65.9762) to (-41.6791, -74.4658) ccw
    arc A62 centre (-30.5946, -71.6108) radius 4.5 from (-32.5278, -75.6744) to (-31.4067, -67.1847) ccw
    arc A63 centre (-34.1137, -52.431) radius 15 from (-40.558, -65.9762) to (-31.4067, -67.1847) ccw
    arc A64 centre (-38.9721, -89.2196) radius 15 from (-41.6791, -74.4658) to (-32.5278, -75.6744) cw
    circle A65 centre (-30.5946, -71.6108) radius 2.25
    circle A66 centre (-42.4913, -70.0397) radius 2.25
    arc A67 centre (-370.1292, -14.2136) radius 4.5 from (-365.9539, -12.5353) to (-372.5313, -18.0188) ccw
    arc A68 centre (-352.036, -6.9412) radius 15 from (-365.9539, -12.5353) to (-360.043, -19.6254) ccw
    arc A69 centre (-380.5383, -30.703) radius 15 from (-372.5313, -18.0188) to (-366.6205, -25.1089) cw
    arc A70 centre (-362.4451, -23.4307) radius 4.5 from (-366.6205, -25.1089) to (-360.043, -19.6254) ccw
    circle A71 centre (-362.4451, -23.4307) radius 2.25
    circle A72 centre (-370.1292, -14.2136) radius 2.25
    reference projected circle E2 centre (-6.7932, -74.6917) radius 2.25 from edge [face of Pad1 from Sketch2.A22 | end face of Pad1]
    reference projected circle E3 centre (-18.6979, -73.1819) radius 2.25 from edge [face of Pad1 from Sketch2.A23 | end face of Pad1]
    point P108 (-30.5946, -71.6108)
    point P109 (-31.0799, -62.4228)
    reference projected circle E4 centre (-30.5946, -71.6108) radius 2.25 from edge [face of Pad1 from Sketch2.A24 | end face of Pad1]
    reference projected circle E5 centre (-42.4913, -70.0397) radius 2.25 from edge [face of Pad1 from Sketch2.A25 | end face of Pad1]
    point P110 (-54.388, -68.4686)
    reference projected circle E6 centre (-54.388, -68.4686) radius 2.25 from edge [face of Pad1 from Sketch2.A26 | end face of Pad1]
    point P117 (-54.388, -68.4686)
    point P118 (-54.8733, -59.2806)
    arc A73 centre (-66.2847, -66.8976) radius 4.5 from (-64.3514, -62.834) to (-65.4726, -71.3237) ccw
    arc A74 centre (-54.388, -68.4686) radius 4.5 from (-56.3213, -72.5322) to (-55.2001, -64.0425) ccw
    arc A75 centre (-57.9072, -49.2888) radius 15 from (-64.3514, -62.834) to (-55.2001, -64.0425) ccw
    arc A76 centre (-62.7655, -86.0774) radius 15 from (-65.4726, -71.3237) to (-56.3213, -72.5322) cw
    circle A77 centre (-54.388, -68.4686) radius 2.25
    circle A78 centre (-66.2847, -66.8976) radius 2.25
    point P127 (-78.1814, -65.3265)
    point P128 (-78.6667, -56.1384)
    arc A79 centre (-90.0781, -63.7554) radius 4.5 from (-88.1448, -59.6918) to (-89.266, -68.1815) ccw
    arc A80 centre (-78.1814, -65.3265) radius 4.5 from (-80.1147, -69.39) to (-78.9935, -60.9003) ccw
    arc A81 centre (-81.7006, -46.1466) radius 15 from (-88.1448, -59.6918) to (-78.9935, -60.9003) ccw
    arc A82 centre (-86.5589, -82.9352) radius 15 from (-89.266, -68.1815) to (-80.1147, -69.39) cw
    circle A83 centre (-78.1814, -65.3265) radius 2.25
    circle A84 centre (-90.0781, -63.7554) radius 2.25
    point P137 (-101.9748, -62.1843)
    point P138 (-102.4601, -52.9962)
    arc A85 centre (-113.8715, -60.6132) radius 4.5 from (-111.9382, -56.5496) to (-113.0594, -65.0393) ccw
    arc A86 centre (-101.9748, -62.1843) radius 4.5 from (-103.9081, -66.2478) to (-102.7869, -57.7582) ccw
    arc A87 centre (-105.494, -43.0045) radius 15 from (-111.9382, -56.5496) to (-102.7869, -57.7582) ccw
    arc A88 centre (-110.3523, -79.793) radius 15 from (-113.0594, -65.0393) to (-103.9081, -66.2478) cw
    circle A89 centre (-101.9748, -62.1843) radius 2.25
    circle A90 centre (-113.8715, -60.6132) radius 2.25
    point P147 (-125.7682, -59.0421)
    point P148 (-126.2535, -49.8541)
    arc A91 centre (-137.6649, -57.471) radius 4.5 from (-135.7317, -53.4074) to (-136.8528, -61.8971) ccw
    arc A92 centre (-125.7682, -59.0421) radius 4.5 from (-127.7015, -63.1056) to (-126.5803, -54.616) ccw
    arc A93 centre (-129.2874, -39.8623) radius 15 from (-135.7317, -53.4074) to (-126.5803, -54.616) ccw
    arc A94 centre (-134.1457, -76.6508) radius 15 from (-136.8528, -61.8971) to (-127.7015, -63.1056) cw
    circle A95 centre (-125.7682, -59.0421) radius 2.25
    circle A96 centre (-137.6649, -57.471) radius 2.25
    point P157 (-149.5616, -55.8999)
    point P158 (-150.0469, -46.7119)
    arc A97 centre (-161.4584, -54.3288) radius 4.5 from (-159.5251, -50.2653) to (-160.6462, -58.7549) ccw
    arc A98 centre (-149.5616, -55.8999) radius 4.5 from (-151.4949, -59.9635) to (-150.3738, -51.4738) ccw
    arc A99 centre (-153.0808, -36.7201) radius 15 from (-159.5251, -50.2653) to (-150.3738, -51.4738) ccw
    arc A100 centre (-157.9392, -73.5086) radius 15 from (-160.6462, -58.7549) to (-151.4949, -59.9635) cw
    circle A101 centre (-149.5616, -55.8999) radius 2.25
    circle A102 centre (-161.4584, -54.3288) radius 2.25
    point P167 (-173.3551, -52.7577)
    point P168 (-173.8404, -43.5697)
    arc A103 centre (-185.2518, -51.1866) radius 4.5 from (-183.3185, -47.1231) to (-184.4396, -55.6127) ccw
    arc A104 centre (-173.3551, -52.7577) radius 4.5 from (-175.2883, -56.8213) to (-174.1672, -48.3316) ccw
    arc A105 centre (-176.8742, -33.5779) radius 15 from (-183.3185, -47.1231) to (-174.1672, -48.3316) ccw
    arc A106 centre (-181.7326, -70.3664) radius 15 from (-184.4396, -55.6127) to (-175.2883, -56.8213) cw
    circle A107 centre (-173.3551, -52.7577) radius 2.25
    circle A108 centre (-185.2518, -51.1866) radius 2.25
    point P177 (-197.1485, -49.6155)
    point P178 (-197.6338, -40.4275)
    arc A109 centre (-209.0452, -48.0444) radius 4.5 from (-207.1119, -43.9809) to (-208.2331, -52.4706) ccw
    arc A110 centre (-197.1485, -49.6155) radius 4.5 from (-199.0818, -53.6791) to (-197.9606, -45.1894) ccw
    arc A111 centre (-200.6677, -30.4357) radius 15 from (-207.1119, -43.9809) to (-197.9606, -45.1894) ccw
    arc A112 centre (-205.526, -67.2243) radius 15 from (-208.2331, -52.4706) to (-199.0818, -53.6791) cw
    circle A113 centre (-197.1485, -49.6155) radius 2.25
    circle A114 centre (-209.0452, -48.0444) radius 2.25
    point P187 (-220.9419, -46.4734)
    point P188 (-221.4272, -37.2853)
    arc A115 centre (-232.8386, -44.9023) radius 4.5 from (-230.9053, -40.8387) to (-232.0265, -49.3284) ccw
    arc A116 centre (-220.9419, -46.4734) radius 4.5 from (-222.8752, -50.5369) to (-221.754, -42.0472) ccw
    arc A117 centre (-224.4611, -27.2935) radius 15 from (-230.9053, -40.8387) to (-221.754, -42.0472) ccw
    arc A118 centre (-229.3194, -64.0821) radius 15 from (-232.0265, -49.3284) to (-222.8752, -50.5369) cw
    circle A119 centre (-220.9419, -46.4734) radius 2.25
    circle A120 centre (-232.8386, -44.9023) radius 2.25
    point P197 (-244.7353, -43.3312)
    point P198 (-245.2206, -34.1431)
    arc A121 centre (-256.632, -41.7601) radius 4.5 from (-254.6987, -37.6965) to (-255.8199, -46.1862) ccw
    arc A122 centre (-244.7353, -43.3312) radius 4.5 from (-246.6686, -47.3947) to (-245.5474, -38.9051) ccw
    arc A123 centre (-248.2545, -24.1514) radius 15 from (-254.6987, -37.6965) to (-245.5474, -38.9051) ccw
    arc A124 centre (-253.1128, -60.9399) radius 15 from (-255.8199, -46.1862) to (-246.6686, -47.3947) cw
    circle A125 centre (-244.7353, -43.3312) radius 2.25
    circle A126 centre (-256.632, -41.7601) radius 2.25
    point P207 (-268.5287, -40.189)
    point P208 (-269.014, -31.0009)
    arc A127 centre (-280.4254, -38.6179) radius 4.5 from (-278.4922, -34.5543) to (-279.6133, -43.044) ccw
